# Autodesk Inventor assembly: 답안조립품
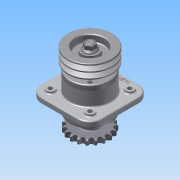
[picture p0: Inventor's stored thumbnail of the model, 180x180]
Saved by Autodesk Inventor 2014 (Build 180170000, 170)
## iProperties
Created: 2015-09
Part Number: 답안조립품
Document SubType Name: Assembly
Designer: study
Author: study
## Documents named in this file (11)
- C:\Users\study\Desktop\450909V1015\답안조립품.iam
- C:\Users\study\Desktop\450909V1015\1-본체.ipt
- C:\Users\study\Desktop\450909V1015\6-베어링 6206.ipt
- C:\Users\study\Desktop\450909V1015\3-축.ipt
- C:\Users\study\Desktop\450909V1015\2-커버.ipt
- C:\Users\study\Desktop\450909V1015\8-오일실 30x42.ipt
- C:\Users\study\Desktop\450909V1015\11-키 6x6.ipt
- C:\Users\study\Desktop\450909V1015\4-V벨트풀리.ipt
- C:\Users\study\Desktop\450909V1015\5-체인 스프로킷.ipt
- C:\Users\study\Desktop\450909V1015\9-M16-너트.ipt
- C:\Users\study\Desktop\450909V1015\10-M6.ipt
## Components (22 placed, 10 different names)
1. 1-본체:1
2. 6-베어링 6206:1
3. 6-베어링 6206:2
4. 3-축:1 — 각도:1, 각도:2
5. 2-커버:1
6. 2-커버:2
7. 8-8-오일실 30x42:1
8. 8-8-오일실 30x42:2
9. 11-키 6x6:1 — 각도:2, 각도:3
10. 11-키 6x6:2 — 각도:1, 각도:4
11. 4-V벨트풀리:1 — 각도:3
12. 5-체인 스프로킷:1 — 각도:4
13. 9-M16 너트:1
14. 9-M16 너트:2
15. 10-M6:2
16. 10-M6:1
17. 10-M6:3
18. 10-M6:4
19. 10-M6:5
20. 10-M6:6
21. 10-M6:7
22. 10-M6:8
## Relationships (4: Angle 4)
- 각도:1 [Angle]: 3-축:1 ↔ 11-키 6x6:2
- 각도:2 [Angle]: 3-축:1 ↔ 11-키 6x6:1
- 각도:3 [Angle]: 11-키 6x6:1 ↔ 4-V벨트풀리:1
- 각도:4 [Angle]: 11-키 6x6:2 ↔ 5-체인 스프로킷:1
